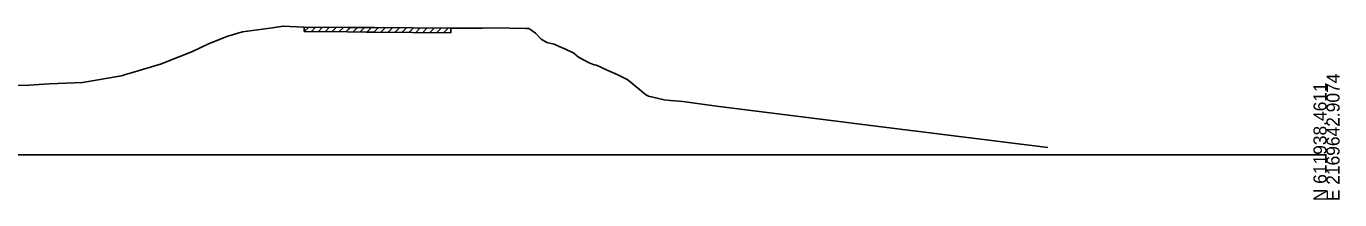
# Model space of a CAD drawing. Extents: x -26 to 6803, y -10 to 19606.
# Drawn here: x 2520.5 to 2802.8, y 3990.3 to 4027.7 of the extents above; entities that cross this region are included whole.
import ezdxf

# ---------------------------------------------------------------- set-up
doc = ezdxf.new("R2010")
doc.units = 0
for name, color, linetype in [('RD_GPK_XS_Cell', 7, 'Continuous'), ('RD_XS_ExGround', 7, 'Continuous'), ('RD_XS_ExPaveRet', 7, 'Continuous')]:
    doc.layers.add(name, color=color, linetype=linetype)

msp = doc.modelspace()

# ---------------------------------------------------------------- linework, layer by layer
at = {"layer": 'RD_GPK_XS_Cell'}
msp.add_line((2400, 4000), (2800, 4000), dxfattribs=at)
at = {"layer": 'RD_XS_ExGround'}
msp.add_lwpolyline([(2516.23, 4014.89), (2521.07, 4015.01), (2525.43, 4015.28), (2532.59, 4015.56), (2540.51, 4016.91), (2540.94, 4016.98), (2541.81, 4017.3), (2543.35, 4017.7), (2549.58, 4019.59), (2550.05, 4019.78), (2556.2, 4022.25), (2559.66, 4023.88), (2563.79, 4025.52), (2566.97, 4026.5), (2573.42, 4027.34), (2575.64, 4027.69), (2580.2, 4027.52), (2589.55, 4027.45), (2593.6, 4027.41), (2595.34, 4027.4), (2611.76, 4027.27), (2618.54, 4027.28), (2620.98, 4027.33), (2627.85, 4027.23), (2628.49, 4027.22), (2629.13, 4026.75), (2629.95, 4026.22), (2631.15, 4024.91), (2632.38, 4024.15), (2634, 4023.81), (2635.04, 4023.33), (2636.4, 4022.72), (2638.17, 4021.86), (2639.2, 4021.03), (2641.48, 4019.83), (2642.56, 4019.37), (2643.03, 4019.3), (2645.35, 4018.21), (2647.67, 4017.22), (2649.64, 4016.24), (2650.21, 4015.78), (2653.6, 4013.01), (2654.21, 4012.59), (2657.58, 4011.81), (2658.95, 4011.66), (2661.59, 4011.48), (2668.87, 4010.47), (2688.92, 4007.97), (2706.07, 4005.8), (2740.08, 4001.58)], dxfattribs=at)
at = {"layer": 'RD_XS_ExPaveRet'}
for p, q in [((2580.2, 4026.52), (2580.2, 4027.52)), ((2580.2, 4026.52), (2581.19, 4027.51)), ((2580.2, 4026.52), (2589.55, 4026.45)), ((2581.7, 4026.51), (2582.69, 4027.5)), ((2583.2, 4026.49), (2584.19, 4027.49)), ((2584.7, 4026.48), (2585.69, 4027.48)), ((2586.2, 4026.47), (2587.19, 4027.47)), ((2587.7, 4026.46), (2588.69, 4027.45)), ((2589.2, 4026.45), (2590.19, 4027.44)), ((2589.55, 4026.45), (2593.6, 4026.41)), ((2590.7, 4026.44), (2591.69, 4027.43)), ((2592.2, 4026.42), (2593.19, 4027.41)), ((2593.7, 4026.41), (2594.69, 4027.4)), ((2595.2, 4026.4), (2596.19, 4027.39)), ((2596.7, 4026.39), (2597.69, 4027.38)), ((2598.2, 4026.37), (2599.19, 4027.37)), ((2599.7, 4026.36), (2600.69, 4027.35)), ((2601.2, 4026.35), (2602.19, 4027.34)), ((2602.7, 4026.34), (2603.69, 4027.33)), ((2604.2, 4026.33), (2605.19, 4027.32)), ((2605.7, 4026.32), (2606.69, 4027.31)), ((2607.2, 4026.3), (2608.19, 4027.3)), ((2608.7, 4026.29), (2609.69, 4027.28)), ((2610.2, 4026.28), (2611.19, 4027.27)), ((2611.76, 4027.27), (2611.76, 4026.27)), ((2593.6, 4026.41), (2595.34, 4026.4)), ((2595.34, 4026.4), (2611.76, 4026.27))]:
    msp.add_line(p, q, dxfattribs=at)

# ---------------------------------------------------------------- texts
at = {"layer": 'RD_GPK_XS_Cell'}
for s, p in [('N 611938.4611', (2800, 3990)), ('E 2169642.9074', (2802.8, 3990))]:
    msp.add_text(s, height=2.8, rotation=90, dxfattribs=at).set_placement(p)

doc.saveas('drawing.dxf')
